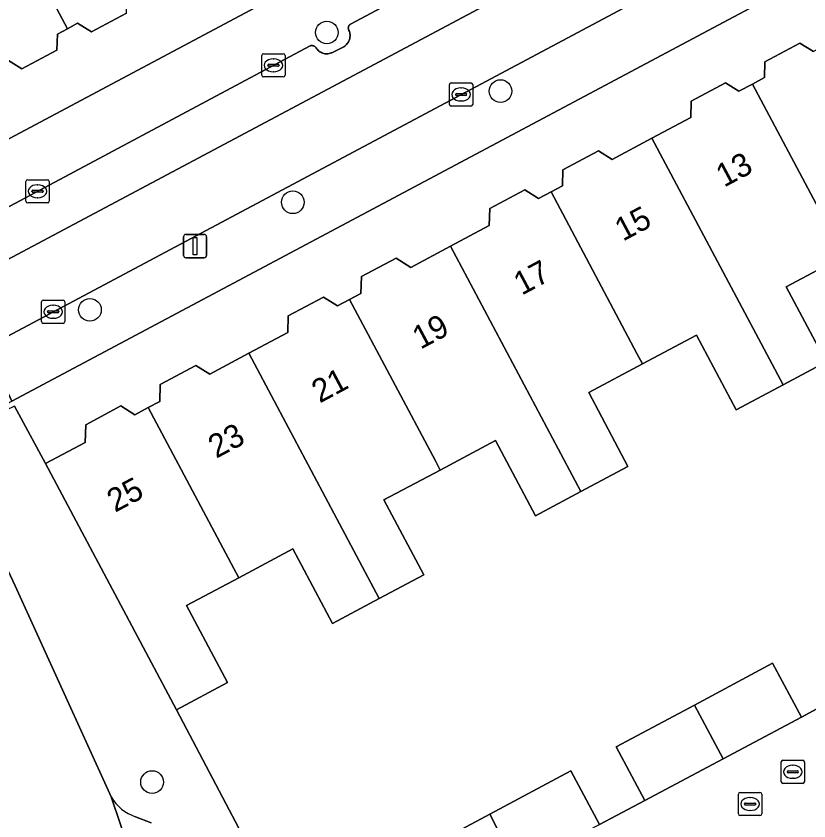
# Model space of a CAD drawing. Extents: x 160304 to 160955, y 383684 to 384161.
# Drawn here: x 160683.55 to 160717.68, y 383894.83 to 383929.45 of the extents above; entities that cross this region are included whole.
import ezdxf

# ---------------------------------------------------------------- set-up
doc = ezdxf.new("R2010")
doc.units = 0
for name, color, linetype in [('IMGEO_Boom', 7, 'Continuous'), ('IMGEO_Erf', 7, 'Continuous'), ('IMGEO_Kolk', 7, 'Continuous'), ('IMGEO_Lichtmast', 7, 'Continuous'), ('IMGEO_Pand', 7, 'Continuous'), ('IMGEO_Pand_nummerreeks', 7, 'Continuous'), ('IMGEO_Parkeervlak_open', 7, 'Continuous'), ('IMGEO_Rijbaan_lokaal_open', 7, 'Continuous'), ('IMGEO_Rioolput', 7, 'Continuous'), ('IMGEO_Voetpad_open', 7, 'Continuous')]:
    doc.layers.add(name, color=color, linetype=linetype)

msp = doc.modelspace()

# ---------------------------------------------------------------- linework, layer by layer
at = {"layer": 'IMGEO_Boom'}
for centre in [(160696.927, 383928.749), (160704.402, 383926.227), (160695.463, 383921.445), (160686.729, 383916.816), (160689.405, 383896.502)]:
    msp.add_circle(centre, 0.489, dxfattribs=at)
at = {"layer": 'IMGEO_Erf'}
for points in [[(160678.654, 383921.738), (160737.631, 383953.138)], [(160731.321, 383938.411), (160683.374, 383912.887)], [(160688.301, 383929.573), (160686.799, 383928.773), (160686.2, 383929.147), (160685.76, 383928.912), (160685.329, 383928.683), (160685.306, 383927.99), (160683.802, 383927.189), (160683.231, 383927.546)], [(160683.49, 383912.67), (160684.818, 383910.205), (160686.528, 383911.116), (160686.554, 383911.876), (160688.063, 383912.68), (160688.66, 383912.307), (160689.243, 383912.618), (160689.732, 383912.878), (160689.757, 383913.61), (160691.288, 383914.425), (160691.887, 383914.051), (160693.571, 383914.948), (160695.241, 383915.837), (160695.265, 383916.553), (160696.785, 383917.363), (160697.391, 383916.985), (160697.907, 383917.26), (160698.396, 383917.52), (160698.421, 383918.248), (160699.904, 383919.038), (160700.535, 383918.644), (160702.252, 383919.558), (160703.919, 383920.446), (160703.944, 383921.179), (160705.445, 383921.979), (160706.038, 383921.609), (160706.576, 383921.895), (160707.068, 383922.157), (160707.091, 383922.846), (160708.615, 383923.657), (160709.207, 383923.288), (160710.917, 383924.199), (160712.59, 383925.09), (160712.614, 383925.791), (160714.091, 383926.577), (160714.66, 383926.222), (160715.243, 383926.532), (160715.761, 383926.808), (160715.784, 383927.492), (160717.288, 383928.293), (160717.869, 383927.93)], [(160719.179, 383919.131), (160716.698, 383917.81), (160718.421, 383914.575), (160716.561, 383913.585), (160714.547, 383912.512), (160712.835, 383915.726), (160710.514, 383914.49), (160708.196, 383913.255), (160709.886, 383910.082), (160707.863, 383909.004), (160705.903, 383907.96), (160704.182, 383911.191), (160701.807, 383909.926), (160699.384, 383908.636), (160701.1, 383905.415), (160699.183, 383904.394), (160697.176, 383903.325), (160695.468, 383906.532), (160693.139, 383905.291), (160690.886, 383904.091), (160692.649, 383900.78), (160690.46, 383899.614), (160695.264, 383890.492)], [(160700.695, 383893.38), (160703.947, 383895.116), (160707.434, 383896.978), (160708.662, 383894.677), (160710.608, 383895.703), (160709.375, 383898.014), (160712.748, 383899.815), (160716.115, 383901.613), (160717.356, 383899.288), (160719.301, 383900.356)]]:
    msp.add_lwpolyline(points, dxfattribs=at)
at = {"layer": 'IMGEO_Kolk'}
for p, q in [((160694.2, 383927.836), (160695.052, 383927.836)), ((160694.125, 383926.91), (160694.125, 383927.762)), ((160694.613, 383927.616), (160694.638, 383927.616)), ((160695.126, 383927.762), (160695.126, 383926.91)), ((160694.384, 383927.33), (160694.384, 383927.342)), ((160694.822, 383927.293), (160694.424, 383927.293)), ((160694.427, 383927.379), (160694.825, 383927.379)), ((160694.868, 383927.342), (160694.868, 383927.33)), ((160695.052, 383926.836), (160694.2, 383926.836)), ((160694.636, 383927.056), (160694.611, 383927.056)), ((160702.204, 383925.656), (160702.204, 383926.508)), ((160702.279, 383926.582), (160703.131, 383926.582)), ((160703.205, 383926.508), (160703.205, 383925.656)), ((160702.463, 383926.076), (160702.463, 383926.088)), ((160702.506, 383926.125), (160702.904, 383926.125)), ((160702.692, 383926.362), (160702.717, 383926.362)), ((160702.947, 383926.088), (160702.947, 383926.076)), ((160702.901, 383926.039), (160702.503, 383926.039)), ((160702.715, 383925.802), (160702.69, 383925.802)), ((160703.131, 383925.582), (160702.279, 383925.582)), ((160683.975, 383921.49), (160683.975, 383922.342)), ((160684.05, 383922.416), (160684.902, 383922.416)), ((160684.976, 383922.342), (160684.976, 383921.49)), ((160684.277, 383921.959), (160684.675, 383921.959)), ((160684.463, 383922.196), (160684.488, 383922.196)), ((160684.234, 383921.91), (160684.234, 383921.922)), ((160684.672, 383921.873), (160684.274, 383921.873)), ((160684.486, 383921.636), (160684.461, 383921.636)), ((160684.718, 383921.922), (160684.718, 383921.91)), ((160684.902, 383921.416), (160684.05, 383921.416)), ((160684.648, 383916.309), (160684.648, 383917.161)), ((160684.723, 383917.235), (160685.575, 383917.235)), ((160685.649, 383917.161), (160685.649, 383916.309)), ((160684.907, 383916.729), (160684.907, 383916.741)), ((160684.95, 383916.778), (160685.348, 383916.778)), ((160685.136, 383917.015), (160685.161, 383917.015)), ((160685.391, 383916.741), (160685.391, 383916.729)), ((160685.345, 383916.692), (160684.947, 383916.692)), ((160685.159, 383916.455), (160685.134, 383916.455)), ((160685.575, 383916.235), (160684.723, 383916.235)), ((160714.641, 383895.131), (160714.641, 383895.983)), ((160714.716, 383896.057), (160715.568, 383896.057)), ((160715.642, 383895.983), (160715.642, 383895.131)), ((160715.129, 383895.837), (160715.154, 383895.837)), ((160714.9, 383895.551), (160714.9, 383895.563)), ((160715.338, 383895.514), (160714.94, 383895.514)), ((160714.943, 383895.6), (160715.341, 383895.6)), ((160715.152, 383895.277), (160715.127, 383895.277)), ((160715.384, 383895.563), (160715.384, 383895.551)), ((160715.568, 383895.057), (160714.716, 383895.057))]:
    msp.add_line(p, q, dxfattribs=at)
for points in [[(160694.2, 383927.836), (160695.052, 383927.836)], [(160694.125, 383926.91), (160694.125, 383927.762)], [(160695.126, 383927.762), (160695.126, 383926.91)], [(160695.052, 383926.836), (160694.2, 383926.836)], [(160702.204, 383925.656), (160702.204, 383926.508)], [(160702.279, 383926.582), (160703.131, 383926.582)], [(160703.205, 383926.508), (160703.205, 383925.656)], [(160703.131, 383925.582), (160702.279, 383925.582)], [(160683.975, 383921.49), (160683.975, 383922.342)], [(160684.05, 383922.416), (160684.902, 383922.416)], [(160684.976, 383922.342), (160684.976, 383921.49)], [(160684.902, 383921.416), (160684.05, 383921.416)], [(160684.648, 383916.309), (160684.648, 383917.161)], [(160684.723, 383917.235), (160685.575, 383917.235)], [(160685.649, 383917.161), (160685.649, 383916.309)], [(160685.575, 383916.235), (160684.723, 383916.235)], [(160714.641, 383895.131), (160714.641, 383895.983)], [(160714.716, 383896.057), (160715.568, 383896.057)], [(160715.642, 383895.983), (160715.642, 383895.131)], [(160715.568, 383895.057), (160714.716, 383895.057)]]:
    msp.add_lwpolyline(points, dxfattribs=at)
for centre, radius, start, end in [((160694.202, 383927.76), 0.0765, 91.552, 178.448), ((160694.202, 383927.76), 0.0765, 91.552, 178.448), ((160695.05, 383927.76), 0.0765, 1.552, 88.448), ((160695.05, 383927.76), 0.0765, 1.552, 88.448), ((160694.424, 383927.339), 0.0403, 85.8775, 175.7526), ((160694.421, 383927.329), 0.0366, 178.938, 274.7102), ((160694.825, 383927.336), 0.043, 264.8664, 352.4533), ((160694.829, 383927.341), 0.0386, 1.7309, 96.639), ((160694.202, 383926.912), 0.0765, 181.552, 268.448), ((160694.202, 383926.912), 0.0765, 181.552, 268.448), ((160695.05, 383926.912), 0.0765, 271.552, 358.448), ((160695.05, 383926.912), 0.0765, 271.552, 358.448), ((160702.281, 383926.506), 0.0765, 91.552, 178.448), ((160702.281, 383926.506), 0.0765, 91.552, 178.448), ((160703.129, 383926.506), 0.0765, 1.552, 88.448), ((160703.129, 383926.506), 0.0765, 1.552, 88.448), ((160702.503, 383926.085), 0.0403, 85.8775, 175.7526), ((160702.908, 383926.087), 0.0386, 1.7309, 96.639), ((160702.5, 383926.075), 0.0366, 178.938, 274.7102), ((160702.904, 383926.082), 0.043, 264.8664, 352.4533), ((160702.281, 383925.658), 0.0765, 181.552, 268.448), ((160702.281, 383925.658), 0.0765, 181.552, 268.448), ((160703.129, 383925.658), 0.0765, 271.552, 358.448), ((160703.129, 383925.658), 0.0765, 271.552, 358.448), ((160684.052, 383922.34), 0.0765, 91.552, 178.448), ((160684.052, 383922.34), 0.0765, 91.552, 178.448), ((160684.9, 383922.34), 0.0765, 1.552, 88.448), ((160684.9, 383922.34), 0.0765, 1.552, 88.448), ((160684.274, 383921.919), 0.0403, 85.8775, 175.7526), ((160684.679, 383921.921), 0.0386, 1.7309, 96.639), ((160684.271, 383921.909), 0.0366, 178.938, 274.7102), ((160684.675, 383921.916), 0.043, 264.8664, 352.4533), ((160684.052, 383921.492), 0.0765, 181.552, 268.448), ((160684.052, 383921.492), 0.0765, 181.552, 268.448), ((160684.9, 383921.492), 0.0765, 271.552, 358.448), ((160684.9, 383921.492), 0.0765, 271.552, 358.448), ((160684.725, 383917.159), 0.0765, 91.552, 178.448), ((160684.725, 383917.159), 0.0765, 91.552, 178.448), ((160685.573, 383917.159), 0.0765, 1.552, 88.448), ((160685.573, 383917.159), 0.0765, 1.552, 88.448), ((160684.947, 383916.738), 0.0403, 85.8775, 175.7526), ((160685.352, 383916.74), 0.0386, 1.7309, 96.639), ((160684.944, 383916.728), 0.0366, 178.938, 274.7102), ((160685.348, 383916.735), 0.043, 264.8664, 352.4533), ((160684.725, 383916.311), 0.0765, 181.552, 268.448), ((160684.725, 383916.311), 0.0765, 181.552, 268.448), ((160685.573, 383916.311), 0.0765, 271.552, 358.448), ((160685.573, 383916.311), 0.0765, 271.552, 358.448), ((160714.718, 383895.981), 0.0765, 91.552, 178.448), ((160714.718, 383895.981), 0.0765, 91.552, 178.448), ((160715.566, 383895.981), 0.0765, 1.552, 88.448), ((160715.566, 383895.981), 0.0765, 1.552, 88.448), ((160714.94, 383895.56), 0.0403, 85.8775, 175.7526), ((160714.937, 383895.55), 0.0366, 178.938, 274.7102), ((160715.341, 383895.557), 0.043, 264.8664, 352.4533), ((160715.345, 383895.562), 0.0386, 1.7309, 96.639), ((160714.718, 383895.133), 0.0765, 181.552, 268.448), ((160714.718, 383895.133), 0.0765, 181.552, 268.448), ((160715.566, 383895.133), 0.0765, 271.552, 358.448), ((160715.566, 383895.133), 0.0765, 271.552, 358.448)]:
    msp.add_arc(centre, radius, start, end, dxfattribs=at)
for centre, major_axis, ratio, start_param, end_param in [((160694.612, 383927.336), (-0.387, 0.002), 0.722429, 4.712389, 7.853982), ((160694.637, 383927.336), (-0.39, 0.002), 0.717154, 1.570796, 4.712389), ((160702.691, 383926.082), (-0.387, 0.002), 0.722429, 4.712389, 7.853982), ((160702.716, 383926.082), (-0.39, 0.002), 0.717154, 1.570796, 4.712389), ((160684.462, 383921.916), (-0.387, 0.002), 0.722429, 4.712389, 7.853982), ((160684.487, 383921.916), (-0.39, 0.002), 0.717154, 1.570796, 4.712389), ((160685.135, 383916.735), (-0.387, 0.002), 0.722429, 4.712389, 7.853982), ((160685.16, 383916.735), (-0.39, 0.002), 0.717154, 1.570796, 4.712389), ((160715.128, 383895.557), (-0.387, 0.002), 0.722429, 4.712389, 7.853982), ((160715.153, 383895.557), (-0.39, 0.002), 0.717154, 1.570796, 4.712389)]:
    msp.add_ellipse(centre, major_axis=major_axis, ratio=ratio, start_param=start_param, end_param=end_param, dxfattribs=at)
at = {"layer": 'IMGEO_Lichtmast'}
for p, q in [((160690.76, 383919.16), (160690.76, 383919.96)), ((160690.76, 383919.96), (160690.76, 383919.16)), ((160690.86, 383920.06), (160691.65, 383920.06)), ((160691.65, 383920.06), (160690.86, 383920.06)), ((160691.75, 383919.96), (160691.75, 383919.16)), ((160691.75, 383919.16), (160691.75, 383919.96)), ((160691.65, 383919.06), (160690.86, 383919.06)), ((160690.86, 383919.06), (160691.65, 383919.06))]:
    msp.add_line(p, q, dxfattribs=at)
msp.add_lwpolyline([(160691.18, 383919.935), (160691.33, 383919.935), (160691.33, 383919.185), (160691.18, 383919.185), (160691.18, 383919.935)], dxfattribs=at)
for centre, start, end in [((160690.86, 383919.96), 90, 180), ((160690.86, 383919.96), 90, 180), ((160691.65, 383919.96), 0, 90), ((160691.65, 383919.96), 360, 90), ((160690.86, 383919.16), 180, 270), ((160690.86, 383919.16), 180, 270), ((160691.65, 383919.16), 270, 0), ((160691.65, 383919.16), 270, 0)]:
    msp.add_arc(centre, 0.1, start, end, dxfattribs=at)
at = {"layer": 'IMGEO_Pand'}
for points in [[(160689.965, 383931.129), (160684.35, 383941.66), (160682.515, 383940.683), (160684.167, 383937.579), (160681.808, 383936.323), (160681.998, 383935.966), (160685.76, 383928.912), (160686.2, 383929.147), (160686.799, 383928.773), (160688.301, 383929.573), (160688.324, 383930.255)], [(160681.571, 383926.662), (160683.231, 383927.546), (160683.802, 383927.189), (160685.306, 383927.99), (160685.329, 383928.683), (160685.76, 383928.912), (160681.998, 383935.966), (160681.808, 383936.323), (160679.649, 383935.174), (160677.959, 383938.349), (160675.917, 383937.262)], [(160715.243, 383926.532), (160718.946, 383919.569), (160719.179, 383919.131), (160721.59, 383920.415), (160723.27, 383917.261), (160725.194, 383918.285), (160719.581, 383928.842), (160717.869, 383927.93), (160717.288, 383928.293), (160715.784, 383927.492), (160715.761, 383926.808)], [(160715.243, 383926.532), (160714.66, 383926.222), (160714.091, 383926.577), (160712.614, 383925.791), (160712.59, 383925.09), (160710.917, 383924.199), (160716.561, 383913.585), (160718.421, 383914.575), (160716.698, 383917.81), (160719.179, 383919.131), (160718.946, 383919.569)], [(160710.514, 383914.49), (160712.835, 383915.726), (160714.547, 383912.512), (160716.561, 383913.585), (160710.917, 383924.199), (160709.207, 383923.288), (160708.615, 383923.657), (160707.091, 383922.846), (160707.068, 383922.157), (160706.576, 383921.895), (160710.274, 383914.942)], [(160710.514, 383914.49), (160710.274, 383914.942), (160706.576, 383921.895), (160706.038, 383921.609), (160705.445, 383921.979), (160703.944, 383921.179), (160703.919, 383920.446), (160702.252, 383919.558), (160707.863, 383909.004), (160709.886, 383910.082), (160708.196, 383913.255)], [(160707.863, 383909.004), (160702.252, 383919.558), (160700.535, 383918.644), (160699.904, 383919.038), (160698.421, 383918.248), (160698.396, 383917.52), (160697.907, 383917.26), (160701.601, 383910.314), (160701.807, 383909.926), (160704.182, 383911.191), (160705.903, 383907.96)], [(160701.807, 383909.926), (160701.601, 383910.314), (160697.907, 383917.26), (160697.391, 383916.985), (160696.785, 383917.363), (160695.265, 383916.553), (160695.241, 383915.837), (160693.571, 383914.948), (160699.183, 383904.394), (160701.1, 383905.415), (160699.384, 383908.636)], [(160693.139, 383905.291), (160695.468, 383906.532), (160697.176, 383903.325), (160699.183, 383904.394), (160693.571, 383914.948), (160691.887, 383914.051), (160691.288, 383914.425), (160689.757, 383913.61), (160689.732, 383912.878), (160689.243, 383912.618), (160692.928, 383905.688)], [(160693.139, 383905.291), (160692.928, 383905.688), (160689.243, 383912.618), (160688.66, 383912.307), (160688.063, 383912.68), (160686.554, 383911.876), (160686.528, 383911.116), (160684.818, 383910.205), (160690.46, 383899.614), (160692.649, 383900.78), (160690.886, 383904.091)], [(160712.748, 383899.815), (160713.982, 383897.495), (160717.356, 383899.288), (160716.115, 383901.613)], [(160712.748, 383899.815), (160709.375, 383898.014), (160710.608, 383895.703), (160713.982, 383897.495)], [(160703.947, 383895.116), (160705.135, 383892.802), (160706, 383893.262), (160708.517, 383894.6), (160708.662, 383894.677), (160707.434, 383896.978)], [(160703.947, 383895.116), (160700.695, 383893.38), (160701.916, 383891.092), (160705.135, 383892.802)]]:
    msp.add_lwpolyline(points, close=True, dxfattribs=at)
at = {"layer": 'IMGEO_Parkeervlak_open'}
for points in [[(160720.506, 383941.171), (160697.973, 383929.121), (160697.957, 383929.114), (160697.942, 383929.105), (160697.927, 383929.095), (160697.914, 383929.084), (160697.902, 383929.072), (160697.89, 383929.058), (160697.88, 383929.044), (160697.872, 383929.028), (160697.865, 383929.013), (160697.859, 383928.996), (160697.854, 383928.979), (160697.852, 383928.962), (160697.85, 383928.944), (160697.851, 383928.927), (160697.853, 383928.909), (160697.856, 383928.892), (160697.861, 383928.875), (160697.867, 383928.859), (160697.874, 383928.846), (160697.879, 383928.835), (160697.897, 383928.788), (160697.91, 383928.74), (160697.919, 383928.691), (160697.924, 383928.641), (160697.924, 383928.591), (160697.92, 383928.541), (160697.911, 383928.492), (160697.898, 383928.444), (160697.881, 383928.397), (160697.859, 383928.352), (160697.834, 383928.309), (160697.805, 383928.268), (160697.772, 383928.23), (160697.736, 383928.195), (160697.698, 383928.164), (160697.656, 383928.136), (160697.136, 383927.875), (160697.118, 383927.867), (160697.074, 383927.852), (160697.028, 383927.84), (160696.982, 383927.832), (160696.935, 383927.829), (160696.888, 383927.83), (160696.841, 383927.835), (160696.795, 383927.844), (160696.749, 383927.857), (160696.705, 383927.874), (160696.663, 383927.895), (160696.623, 383927.92), (160696.585, 383927.948), (160696.55, 383927.98), (160696.518, 383928.014), (160696.489, 383928.051), (160696.464, 383928.091), (160696.451, 383928.107), (160696.436, 383928.122), (160696.42, 383928.136), (160696.403, 383928.148), (160696.385, 383928.159), (160696.366, 383928.168), (160696.346, 383928.175), (160696.326, 383928.18), (160696.306, 383928.184), (160696.285, 383928.185), (160696.264, 383928.185), (160696.243, 383928.183), (160696.222, 383928.179), (160696.202, 383928.174), (160696.18, 383928.165), (160681.609, 383920.385)], [(160680.921, 383917.781), (160721.467, 383939.366)], [(160687.649, 383895.859), (160690.85, 383886.385)], [(160689.366, 383894.741), (160688.693, 383895.008)]]:
    msp.add_lwpolyline(points, dxfattribs=at)
msp.add_arc((160689.308, 383896.828), 1.921, 210.2957, 251.335, dxfattribs=at)
at = {"layer": 'IMGEO_Rijbaan_lokaal_open'}
msp.add_lwpolyline([(160722.832, 383936.801), (160721.467, 383939.366), (160680.921, 383917.781), (160681.322, 383917.027), (160682.288, 383915.213)], close=True, dxfattribs=at)
for points in [[(160698.422, 383869.109), (160692.989, 383880.566), (160692.837, 383880.981), (160691.168, 383885.513), (160690.888, 383886.273), (160690.85, 383886.385), (160687.649, 383895.859), (160687.584, 383895.992), (160683.512, 383904.948), (160681.85, 383908.464), (160680.633, 383910.769), (160675.442, 383920.557), (160674.779, 383921.821), (160673.701, 383923.877), (160671.738, 383927.276), (160668.265, 383925.27), (160670.852, 383920.79), (160669, 383919.783), (160669.19, 383919.443)], [(160750.253, 383907.138), (160749.311, 383908.902), (160729.17, 383898.199), (160721.445, 383901.495), (160719.301, 383900.356), (160717.356, 383899.288), (160713.982, 383897.495), (160710.608, 383895.703), (160708.662, 383894.677)]]:
    msp.add_lwpolyline(points, dxfattribs=at)
at = {"layer": 'IMGEO_Rioolput'}
for p, q in [((160716.481, 383896.516), (160716.481, 383897.368)), ((160716.556, 383897.442), (160717.408, 383897.442)), ((160717.482, 383897.368), (160717.482, 383896.516)), ((160716.969, 383897.222), (160716.994, 383897.222)), ((160716.74, 383896.936), (160716.74, 383896.948)), ((160717.178, 383896.899), (160716.78, 383896.899)), ((160716.783, 383896.985), (160717.181, 383896.985)), ((160716.992, 383896.662), (160716.967, 383896.662)), ((160717.224, 383896.948), (160717.224, 383896.936)), ((160717.408, 383896.442), (160716.556, 383896.442))]:
    msp.add_line(p, q, dxfattribs=at)
for points in [[(160716.481, 383896.516), (160716.481, 383897.368)], [(160716.556, 383897.442), (160717.408, 383897.442)], [(160717.482, 383897.368), (160717.482, 383896.516)], [(160717.408, 383896.442), (160716.556, 383896.442)]]:
    msp.add_lwpolyline(points, dxfattribs=at)
for centre, radius, start, end in [((160716.558, 383897.366), 0.0765, 91.552, 178.448), ((160716.558, 383897.366), 0.0765, 91.552, 178.448), ((160717.406, 383897.366), 0.0765, 1.552, 88.448), ((160717.406, 383897.366), 0.0765, 1.552, 88.448), ((160716.78, 383896.945), 0.0403, 85.8775, 175.7526), ((160716.777, 383896.935), 0.0366, 178.938, 274.7102), ((160717.181, 383896.942), 0.043, 264.8664, 352.4533), ((160717.185, 383896.947), 0.0386, 1.7309, 96.639), ((160716.558, 383896.518), 0.0765, 181.552, 268.448), ((160716.558, 383896.518), 0.0765, 181.552, 268.448), ((160717.406, 383896.518), 0.0765, 271.552, 358.448), ((160717.406, 383896.518), 0.0765, 271.552, 358.448)]:
    msp.add_arc(centre, radius, start, end, dxfattribs=at)
for centre, major_axis, ratio, start_param, end_param in [((160716.968, 383896.942), (-0.387, 0.002), 0.722429, 4.712389, 7.853982), ((160716.993, 383896.942), (-0.39, 0.002), 0.717154, 1.570796, 4.712389)]:
    msp.add_ellipse(centre, major_axis=major_axis, ratio=ratio, start_param=start_param, end_param=end_param, dxfattribs=at)
at = {"layer": 'IMGEO_Voetpad_open'}
for points in [[(160758.663, 383964.313), (160749.64, 383959.525), (160742.754, 383955.863), (160739.222, 383953.985), (160737.631, 383953.138), (160678.654, 383921.738)], [(160681.609, 383920.385), (160696.18, 383928.165), (160696.202, 383928.174), (160696.222, 383928.179), (160696.243, 383928.183), (160696.264, 383928.185), (160696.285, 383928.185), (160696.306, 383928.184), (160696.326, 383928.18), (160696.346, 383928.175), (160696.366, 383928.168), (160696.385, 383928.159), (160696.403, 383928.148), (160696.42, 383928.136), (160696.436, 383928.122), (160696.451, 383928.107), (160696.464, 383928.091), (160696.489, 383928.051), (160696.518, 383928.014), (160696.55, 383927.98), (160696.585, 383927.948), (160696.623, 383927.92), (160696.663, 383927.895), (160696.705, 383927.874), (160696.749, 383927.857), (160696.795, 383927.844), (160696.841, 383927.835), (160696.888, 383927.83), (160696.935, 383927.829), (160696.982, 383927.832), (160697.028, 383927.84), (160697.074, 383927.852), (160697.118, 383927.867), (160697.136, 383927.875), (160697.656, 383928.136), (160697.698, 383928.164), (160697.736, 383928.195), (160697.772, 383928.23), (160697.805, 383928.268), (160697.834, 383928.309), (160697.859, 383928.352), (160697.881, 383928.397), (160697.898, 383928.444), (160697.911, 383928.492), (160697.92, 383928.541), (160697.924, 383928.591), (160697.924, 383928.641), (160697.919, 383928.691), (160697.91, 383928.74), (160697.897, 383928.788), (160697.879, 383928.835), (160697.874, 383928.846), (160697.867, 383928.859), (160697.861, 383928.875), (160697.856, 383928.892), (160697.853, 383928.909), (160697.851, 383928.927), (160697.85, 383928.944), (160697.852, 383928.962), (160697.854, 383928.979), (160697.859, 383928.996), (160697.865, 383929.013), (160697.872, 383929.028), (160697.88, 383929.044), (160697.89, 383929.058), (160697.902, 383929.072), (160697.914, 383929.084), (160697.927, 383929.095), (160697.942, 383929.105), (160697.957, 383929.114), (160697.973, 383929.121), (160720.506, 383941.171)], [(160690.46, 383899.614), (160684.818, 383910.205), (160683.49, 383912.67), (160683.119, 383912.501), (160683.022, 383912.699), (160683.374, 383912.887), (160682.288, 383915.213), (160681.322, 383917.027), (160679.202, 383915.859), (160681.624, 383911.294), (160680.633, 383910.769), (160681.85, 383908.464), (160683.512, 383904.948), (160687.584, 383895.992), (160687.649, 383895.859)], [(160690.85, 383886.385), (160690.888, 383886.273), (160691.168, 383885.513), (160692.191, 383885.89), (160693.86, 383881.358), (160696.844, 383882.915), (160699.572, 383884.396), (160697.29, 383888.613), (160696.493, 383888.189), (160695.264, 383890.492), (160690.46, 383899.614)], [(160688.693, 383895.008), (160689.366, 383894.741)]]:
    msp.add_lwpolyline(points, dxfattribs=at)
msp.add_lwpolyline([(160731.321, 383938.411), (160731.813, 383938.673), (160732.617, 383939.108), (160733.152, 383939.46), (160733.256, 383939.529), (160743.868, 383945.177), (160746.679, 383946.631), (160764.306, 383956.019), (160763.531, 383958.431), (160746.712, 383949.534), (160747.214, 383948.6), (160742.958, 383946.316), (160742.456, 383947.25), (160725.268, 383938.098), (160722.832, 383936.801), (160682.288, 383915.213), (160683.374, 383912.887)], close=True, dxfattribs=at)
msp.add_arc((160689.308, 383896.828), 1.921, 210.2957, 251.335, dxfattribs=at)

# ---------------------------------------------------------------- texts
at = {"layer": 'IMGEO_Pand_nummerreeks'}
for s, p in [('13', (160714.024, 383922.07)), ('15', (160709.668, 383919.746)), ('17', (160705.313, 383917.422)), ('19', (160700.957, 383915.098)), ('21', (160696.621, 383912.785)), ('23', (160692.166, 383910.408)), ('25', (160687.811, 383908.084))]:
    msp.add_text(s, height=1, rotation=28.0827, dxfattribs=at).set_placement(p)

doc.saveas('drawing.dxf')
